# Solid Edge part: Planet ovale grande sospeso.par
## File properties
Title: Planet ovale grande sospeso
Author: DESYS
Template: Iso Part.par
Last saved by: s.pallini
Revision: 11
Application: Solid Edge
Accuracy: 0,990
Tipo di contenuto documento: 0
Document Number: 8109
Revision: 0
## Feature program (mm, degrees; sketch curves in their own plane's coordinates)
lofted protrusion "unnamed LoftedProtrusion 1"
lofted cutout "unnamed LoftedCutout 1"
sketch for "unnamed Protrusion 1" plane through (0, 160, 0) normal (0, 1, 0) x-axis (1, 0, 0)
  arc centre (0, 0) radius 250 from (250, 0) to (250, 0) cw
extrude "unnamed Protrusion 1" add finite 7 along +normal
sketch for "ScavoEstrusione_1" #1 plane through (0, 167, 0) normal (0, 1, 0) x-axis (1, 0, 0)
  arc centre (0, 0) radius 210 from (210, 0) to (210, 0) cw
sketch for "ScavoEstrusione_1" #2 plane through (0, 167, 0) normal (0, 1, 0) x-axis (1, 0, 0)
  circle centre (0, 0) radius 35
extrude "ScavoEstrusione_1" cut finite 50 along -normal
sketch for "Foro_1" plane through (0, 167, 0) normal (0, 1, 0) x-axis (1, 0, 0)
  hole centre (0, 0) bore radius 25
hole "Foro_1" diameter 50 through
fillet "Rotondo_2" radius 15
fillet "Rotondo_3" radius 10
fillet "Rotondo_4" radius 5
fillet "Rotondo_5" radius 15
sketch for "ProtrusioneEstrusa_2" plane through (0, 0, 0) normal (1, 0, 0) x-axis (0, 1, 0)
extrude "ProtrusioneEstrusa_2" add finite 320 symmetric
sketch for "ScavoEstrusione_2" plane through (0, 0, 0) normal (1, 0, 0) x-axis (0, 1, 0)
extrude "ScavoEstrusione_2" cut finite 280 symmetric
sketch for "Foro_2" plane through (0, 0, 44.9962) normal (0, -1, 0) x-axis (-1, 0, 0)
hole "Foro_2" diameter 35 through
sketch for "unnamed Cutout 1" plane through (0, 83.5, 280) normal (0, 0, 1) x-axis (-1, 0, 0)
extrude "unnamed Cutout 1" cut through along -normal
sketch for "unnamed Protrusion 2" plane through (0, 0, 0) normal (1, 0, 0) x-axis (0, 1, 0)
extrude "unnamed Protrusion 2" add to key point symmetric
fillet "Rotondo_7" radius 5
fillet "Rotondo_8" radius 30
fillet "Rotondo_9" radius 10
fillet "Rotondo_10" radius 10
fillet "Rotondo_11" radius 5
fillet "Rotondo_12" radius 5
sketch for "ScavoEstrusione_4" plane through (0, 0, 0) normal (0, 0, 1) x-axis (1, 0, 0)
  circle centre (0, 25) radius 10
extrude "ScavoEstrusione_4" cut finite 165 along +normal
fillet "Rotondo_18" radius 20
fillet "Rotondo_19" radius 10
sketch for "unnamed Cutout 2" #1 plane through (0, 86, 280) normal (0, 0, 1) x-axis (-1, 0, 0)
sketch for "unnamed Cutout 2" #2 plane through (0, 86, 280) normal (0, 0, 1) x-axis (-1, 0, 0)
extrude "unnamed Cutout 2" cut through along -normal
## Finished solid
Body 1: solid body, 113 faces, 255 edges, 143 vertices.
  Faces by surface: cylinder 36, blend 30, plane 21, torus 13, sphere 8, spline 4, swept 1
  Edges by curve: circle 88, intersection 80, line 71, ellipse 8, curve on surface 6, spline 2
Bounding box of the edges (mm; curved faces can reach further): 659.445 x 167.000 x 470.659, from (-329.7222, 0, -190.6592) to (329.7226, 167, 280).
Cylindrical faces by radius (mm): R5 x18, R10 x11, R17.5 x1, R25 x1, R35 x1, R105 x1, R148.0234 x2, R191.7668 x1
Toroidal faces (ring radius, tube radius in mm): R5 r5 x2, R22.5 r5 x1, R30 r5 x1, R45 r10 x1, R110 r5 x2, R153.0234 r5 x4, R181.7668 r10 x2
Spherical faces by radius (mm): R5 x6, R10 x2
Planar faces by outward normal: +x 3, +y 7, +z 1, -x 3, -y 3, -z 4
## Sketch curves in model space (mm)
arc centre (0, -49.8604, -18.5294) radius 150 from (0, 100, -25) through (0, 70.6732, -107.8135) to (0, 0, -160)
arc centre (0, -49.8604, 18.5294) radius 150 from (0, 100, 25) through (0, 70.6732, 107.8135) to (0, 0, 160)
arc centre (-0.8924, -399.3291, 0) radius 500 from (25, 100, 0) through (169.9791, 70.5676, 0) to (300, 0, 0)
arc centre (0.8924, -399.3291, 0) radius 500 from (-25, 100, 0) through (-169.9791, 70.5676, 0) to (-300, 0, 0)
circle centre (0, 100, 0) radius 25
ellipse centre (0, 0, 0) radii 300, 160
arc centre (0, 15.7496, -30.777) radius 160 from (0, 0, -190) through (0, 98.2149, -167.8882) to (0, 160, -100)
arc centre (0, 15.7496, 30.777) radius 160 from (0, 0, 190) through (0, 98.2149, 167.8882) to (0, 160, 100)
arc centre (130, 0, 0) radius 200 from (250, 160, 0) through (308.8854, 89.4427, 0) to (330, 0, 0)
arc centre (-130, 0, 0) radius 200 from (-250, 160, 0) through (-308.8854, 89.4427, 0) to (-330, 0, 0)
ellipse centre (0, 160, 0) radii 250, 100
ellipse centre (0, 0, 0) radii 330, 190
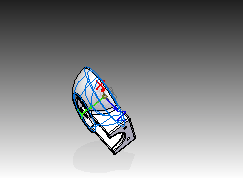
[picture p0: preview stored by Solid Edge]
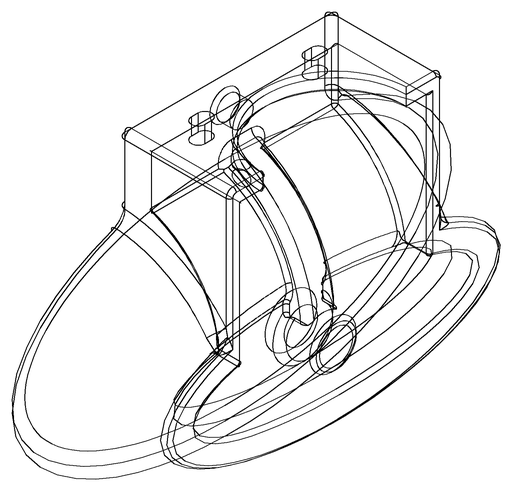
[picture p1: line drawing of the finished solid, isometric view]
